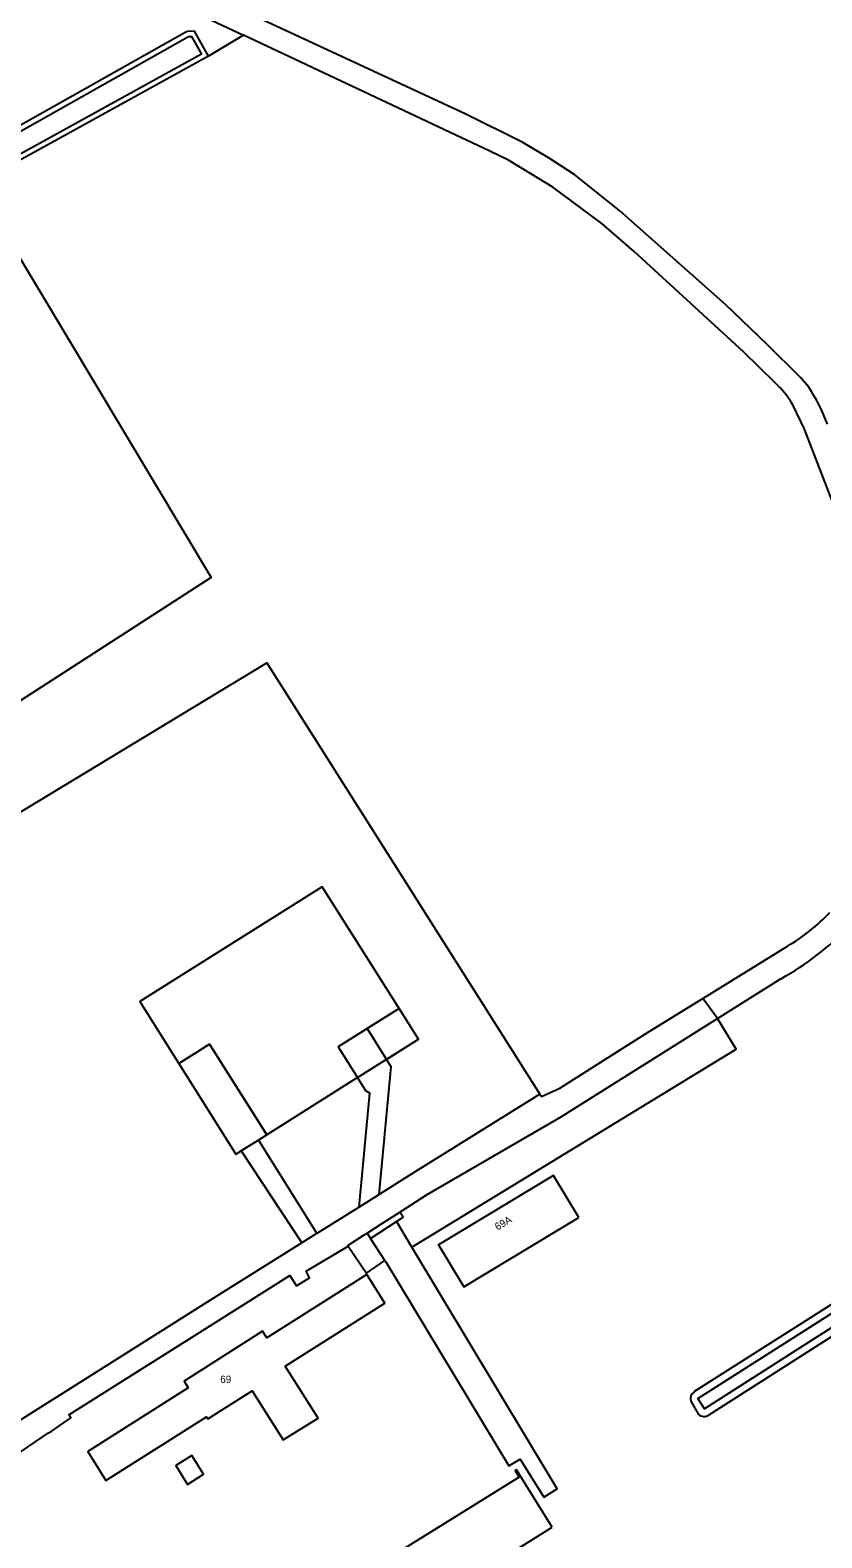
# Model space of a CAD drawing. Extents: x 158132 to 159658, y 385257 to 387209.
# Drawn here: x 158829.4 to 158936.6, y 386709 to 386913.1 of the extents above; entities that cross this region are included whole.
import ezdxf

# ---------------------------------------------------------------- set-up
doc = ezdxf.new("R2010")
doc.units = 0
for name, color, linetype in [('IMGEO_Gemengd_bos', 7, 'Continuous'), ('IMGEO_Loofbos', 7, 'Continuous'), ('IMGEO_Open_loods', 7, 'Continuous'), ('IMGEO_Pand', 7, 'Continuous'), ('IMGEO_Pand_nummerreeks', 7, 'Continuous'), ('IMGEO_Pand_overbouw', 7, 'Continuous'), ('IMGEO_Parkeervlak_halfverhard', 7, 'Continuous'), ('IMGEO_Voetpad_gesloten', 7, 'Continuous'), ('IMGEO_Voetpad_halfverhard', 7, 'Continuous'), ('IMGEO_Voetpad_open', 7, 'Continuous'), ('IMGEO_Waterloop', 7, 'Continuous')]:
    doc.layers.add(name, color=color, linetype=linetype)

msp = doc.modelspace()

# ---------------------------------------------------------------- linework, layer by layer
at = {"layer": 'IMGEO_Gemengd_bos'}
for points in [[(158853.56, 386909.63), (158822.62, 386892.56)], [(158822.53, 386891.44), (158853.93, 386839), (158812.25, 386812.1)], [(159014.06, 386750), (159000.47, 386772.24), (159000, 386772.99), (158997.47, 386777.01), (158962.13, 386755.33), (158952.77, 386750), (158919.3, 386728.73)], [(158921.26, 386725.61), (158959.48, 386750), (158996.15, 386771.99), (159000, 386765.71), (159009.65, 386750), (159034.16, 386711.12)], [(158918.85, 386727.5), (158919.9, 386725.68)]]:
    msp.add_lwpolyline(points, dxfattribs=at)
for centre, radius, start, end in [((158919.9, 386727.81), 1.09, 122.962, 196.4586), ((158920.63, 386726.54), 1.13, 229.5335, 303.9903)]:
    msp.add_arc(centre, radius, start, end, dxfattribs=at)
at = {"layer": 'IMGEO_Loofbos'}
for points in [[(158853.56, 386909.63), (158851.69, 386913.01), (158850.64, 386912.96), (158850.52, 386912.89), (158821.6, 386896.6), (158820.56, 386896.02), (158822.62, 386892.56)], [(158858.32, 386912.48), (158853.56, 386909.63)], [(158779.74, 386777.99), (158861.47, 386827.47), (158898.45, 386769.08)]]:
    msp.add_lwpolyline(points, dxfattribs=at)
at = {"layer": 'IMGEO_Open_loods'}
msp.add_lwpolyline([(158900.1, 386710.42), (158895.26, 386718.18), (158895.09, 386718.08), (158895.64, 386717.2), (158875.13, 386704.45), (158874.63, 386705.26), (158874.46, 386705.16), (158879.3, 386697.4), (158900.1, 386710.42)], dxfattribs=at)
at = {"layer": 'IMGEO_Pand'}
for points in [[(158879.37, 386780.65), (158868.97, 386797.12), (158844.27, 386781.59), (158849.54, 386773.22)], [(158879.37, 386780.65), (158875.05, 386777.94)], [(158875.05, 386777.94), (158871.12, 386775.48), (158873.76, 386771.3)], [(158849.54, 386773.22), (158853.7, 386775.84), (158861.45, 386763.54)], [(158873.76, 386771.3), (158861.45, 386763.54)], [(158903.7, 386752.35), (158900.27, 386758.04), (158884.7, 386748.67), (158888.14, 386742.99), (158903.7, 386752.35)], [(158875.01, 386744.62), (158861.47, 386736.06), (158860.9, 386736.95), (158850.26, 386730.2), (158850.83, 386729.3), (158837.23, 386720.67), (158839.69, 386716.76), (158853.31, 386725.35), (158853.48, 386725.08), (158859.5, 386728.88), (158863.7, 386722.23), (158868.4, 386725.19), (158863.96, 386732.23), (158877.46, 386740.74), (158875.01, 386744.62)], [(158850.74, 386716.22), (158852.91, 386717.59), (158851.3, 386720.15), (158849.13, 386718.78), (158850.74, 386716.22)]]:
    msp.add_lwpolyline(points, dxfattribs=at)
at = {"layer": 'IMGEO_Pand_overbouw'}
for points in [[(158882, 386776.49), (158879.37, 386780.65), (158871.12, 386775.48), (158873.76, 386771.3)], [(158853.7, 386775.84), (158849.54, 386773.22), (158857.29, 386760.92), (158861.45, 386763.54)]]:
    msp.add_lwpolyline(points, close=True, dxfattribs=at)
at = {"layer": 'IMGEO_Parkeervlak_halfverhard'}
msp.add_lwpolyline([(158881.09, 386748.33), (158925.03, 386775.15), (158922.48, 386779.29)], dxfattribs=at)
at = {"layer": 'IMGEO_Voetpad_gesloten'}
for points in [[(158898.45, 386769.08), (158898.66, 386768.76), (158901.14, 386769.86), (158913.25, 386777.55), (158920.51, 386782.03)], [(158922.48, 386779.29), (158920.51, 386782.03)], [(158879.46, 386753.1), (158883.16, 386755.47), (158901.22, 386765.96), (158922.48, 386779.29)], [(158898.45, 386769.08), (158881.12, 386758.25), (158876.69, 386755.48)], [(158876.69, 386755.48), (158873.97, 386753.77)], [(158873.97, 386753.77), (158868.24, 386750.19)], [(158875.04, 386750.25), (158877.14, 386751.61), (158879.46, 386753.1)], [(158875.51, 386749.53), (158879, 386751.81)], [(158879, 386751.81), (158881.06, 386748.39), (158881.09, 386748.33)], [(158868.24, 386750.19), (158867.94, 386750), (158866.2, 386748.91)], [(158872.5, 386748.46), (158872.43, 386748.56), (158874.65, 386750), (158875.04, 386750.25)], [(158784.81, 386691.49), (158789.76, 386694.48), (158796.4, 386698.49), (158803.45, 386702.74), (158820.63, 386715.54), (158831.89, 386723.22), (158832.25, 386723.4), (158834.93, 386725.21), (158834.68, 386725.63), (158850.26, 386735.48), (158864.56, 386744.52), (158865.47, 386743.11), (158867.26, 386744.2), (158866.77, 386745.08), (158872.5, 386748.46)], [(158866.2, 386748.91), (158854.25, 386741.43), (158825.32, 386723.2), (158825.55, 386722.84), (158817.59, 386717.84)], [(158877.45, 386746.53), (158875.51, 386749.53)], [(158877.45, 386746.53), (158877.56, 386746.35), (158894.25, 386718.73), (158895.75, 386719.63), (158898.96, 386714.48), (158900.77, 386715.61), (158881.09, 386748.33)]]:
    msp.add_lwpolyline(points, dxfattribs=at)
at = {"layer": 'IMGEO_Voetpad_halfverhard'}
for points in [[(158877.66, 386773.76), (158882, 386776.49), (158879.37, 386780.65)], [(158849.54, 386773.22), (158857.29, 386760.92), (158858.01, 386761.37)], [(158861.45, 386763.54), (158860.33, 386762.83)], [(158872.5, 386748.46), (158874.95, 386744.8), (158877.45, 386746.53)]]:
    msp.add_lwpolyline(points, dxfattribs=at)
at = {"layer": 'IMGEO_Voetpad_open'}
for points in [[(158840.5, 386921.15), (158846.08, 386918.23), (158858.31, 386912.48), (158858.32, 386912.48)], [(158934.86, 386864.81), (158933.74, 386866.11), (158929.18, 386870.61), (158923.63, 386875.96), (158909.28, 386888.66), (158903.15, 386893.54), (158899.71, 386895.79), (158896.11, 386897.92), (158888.42, 386901.78), (158857.77, 386916)], [(158930.26, 386865.42), (158925.99, 386869.59), (158911.22, 386883.16), (158906.82, 386886.96), (158900.17, 386891.87), (158894.2, 386895.53), (158891.64, 386896.76), (158858.32, 386912.48)], [(158945.74, 386823.06), (158942.78, 386834.37), (158940.11, 386843.29), (158938.31, 386848.58), (158934.26, 386859.12), (158932.73, 386862.32)], [(158920.51, 386782.03), (158931.97, 386789.1)], [(158922.48, 386779.29), (158931.11, 386784.7)], [(158875.05, 386777.94), (158877.58, 386773.89), (158877.66, 386773.76)], [(158876.69, 386755.48), (158878.28, 386772.78), (158877.66, 386773.76)], [(158873.97, 386753.77), (158875.41, 386769.19), (158874.88, 386769.51), (158873.76, 386771.3)], [(158860.33, 386762.83), (158858.01, 386761.37)], [(158860.33, 386762.83), (158868.24, 386750.19)], [(158858.01, 386761.37), (158866.2, 386748.91)], [(158879, 386751.81), (158879.91, 386752.4), (158879.46, 386753.1)], [(158875.04, 386750.25), (158875.51, 386749.53)]]:
    msp.add_lwpolyline(points, dxfattribs=at)
for centre, radius, start, end in [((158921.84, 386856.16), 12.51, 29.4912, 47.72), ((158909.28, 386848.82), 30.17, 21.3147, 32.0068), ((158911.05, 386820.41), 40.96, 299.3244, 331.8962), ((158918.94, 386811.37), 25.79, 300.3437, 316.6431)]:
    msp.add_arc(centre, radius, start, end, dxfattribs=at)
at = {"layer": 'IMGEO_Waterloop'}
for points in [[(158850.84, 386912.27), (158851.29, 386912.29), (158852.61, 386909.9), (158822.88, 386893.5), (158821.53, 386895.76), (158850.84, 386912.27)], [(158958.95, 386750.86), (158920.7, 386726.45), (158919.81, 386727.85), (158953.29, 386749.14), (158962.65, 386754.46), (158997.15, 386775.62), (158999.15, 386772.45), (158999.61, 386771.71), (159013.2, 386749.47), (159036.29, 386713.13), (159036.36, 386712.97), (159036.23, 386712.75), (159034.92, 386711.81), (159010.51, 386750.53), (159000.86, 386766.24), (158996.48, 386773.37), (158958.95, 386750.86)]]:
    msp.add_lwpolyline(points, dxfattribs=at)

# ---------------------------------------------------------------- texts
at = {"layer": 'IMGEO_Pand_nummerreeks'}
msp.add_text('69A', height=1, rotation=30.8538, dxfattribs=at).set_placement((158892.7, 386750.57))
msp.add_text('69', height=1, dxfattribs=at).set_placement((158855.16, 386729.94))

doc.saveas('drawing.dxf')
